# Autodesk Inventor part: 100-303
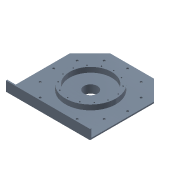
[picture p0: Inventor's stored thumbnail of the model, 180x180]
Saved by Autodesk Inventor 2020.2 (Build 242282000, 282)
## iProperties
Created: 2011-01
Part Number: 100-303
Document SubType Name: Modeling
Designer: F.Stasiak
Density: 1 g/cm^3
Material: Ogólny
Appearance: Stalowoniebieska
Company: Fabian Stasiak CAD Consulting
Manager: www.cadconsulting.pl
Author: F.Stasiak
Subject: Zbiór ćwiczeń. Autodesk Inventor 2020. Kurs podstawowy
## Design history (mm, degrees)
sketch "Szkic1"
  geometry: L1 (250, 0)-(-250, 0); L2 (-250, 0)-(-250, 500); L3 (-250, 500)-(250, 500); L4 (250, 500)-(250, 0); 2 further points
  constraints: 8 end point, 2 perpendicular, 1 coincident, 1 horizontal, 1 midpoint, 1 parallel
  dimensions: "d0" = 500 distance of L1.start L1.end; "d1" = 500 distance of L1.end L2.end
extrude "Wyciągnięcie proste1" new body sketch "Szkic1" distance "d2" = 8; taper "d3" = 0 deg
sketch "Szkic2"
  geometry: L1 (-250, 0)-(-250, 500) reference; L2 (250, 0)-(-250, 0) reference; L3 (250, 500)-(250, 0) reference; L4 (-250, 500)-(250, 500) reference; L5 (-250, 8)-(250, 8); L6 (-250, 0)-(-250, 500) reference; 1 further point
  constraints: 2 end point, 2 point on line, 1 perpendicular
  dimensions: "d4" = 8 distance between parallel lines of L5 L2 (= d2)
extrude "Wyciągnięcie proste2" join sketch "Szkic2" distance "d5" = 50; taper "d6" = 0 deg
chamfer "Faza1" distance "d7" = 120; stored, may be unused: second distance "d8" = 2, angle "d9" = 45 deg
sketch "Szkic3"
  geometry: L1 (130, 500)-(250, 380) reference; L2 (-130, 500)-(130, 500) reference; L3 (-250, 380)-(-130, 500) reference; L4 (-250, 8)-(-250, 380) reference; L5 (-250, 8)-(250, 8) reference; L6 (250, 380)-(250, 8) reference; L7 (0, 500)-(0, 8); C1 r 40 at (0, 254); 1 further point
  constraints: 3 midpoint, 2 end point, 1 centre point
  dimensions: "d10" = 80 diameter of C1
extrude "Wyciągnięcie proste3" cut sketch "Szkic3" extent not by distance; stored distance "d11" = 50; taper "d12" = 0 deg
sketch "Szkic4"
  geometry: C1 r 40 at (0, 254) reference; C2 r 60 at (0, 254); 1 further point
  constraints: 1 centre point
  dimensions: "d13" = 120 diameter of C2
extrude "Wyciągnięcie proste4" join sketch "Szkic4" distance "d14" = 40; taper "d15" = 0 deg
sketch "Szkic5"
  geometry: C1 r 6.5 at (0, 474) reference; 1 further point
hole "Hole1" sketch "Szkic5" at (0, 474) diameter "d16" = 13; stored, may be unused: countersink angle "d20" = 90 deg, drill point angle "d22" = 118 deg; dims "d17" = 6, "d18" = 4, "d19" = 2, "d21" = 8
pattern_circular "Szyk kołowy1" dims angle "d24" = 360 deg
sketch "Szkic6"
  geometry: C1 r 40 at (0, 254) reference; C2 r 150 at (0, 254); C3 r 125 at (0, 254); 1 further point
  constraints: 2 centre point, 2 coincident
  dimensions: "d26" = 300 diameter of C2; "d27" = 250 diameter of C3
extrude "Wyciągnięcie proste5" join sketch "Szkic6" distance "d28" = 30; taper "d29" = 0 deg
sketch "Szkic7" dims "d30" = 275
  geometry: C1 r 125 at (0, 0) reference; 2 further points
  constraints: 1 vertical alignment, 2 other
hole "Hole2" sketch "Szkic7" at (0, 137.5) diameter "d31" = 6.647; stored, may be unused: countersink angle "d35" = 90 deg, drill point angle "d37" = 118 deg; dims "d32" = 17, "d33" = 3.6, "d34" = 2, "d36" = 25
pattern_circular "Szyk kołowy2" dims angle "d39" = 360 deg
node "Otwory1"
node "Otwory2"
node "Bryła1"
node "Pętla rzutowana1"
node "Pętla rzutowana2"
node "Odniesienie1"
sketch "Szkic8"
  geometry: 14 further points
hole "Hole3" sketch "Szkic8" diameter "d41" = 4.917; stored, may be unused: countersink angle "d45" = 90 deg, drill point angle "d47" = 120 deg; dims "d42" = 9.5, "d43" = 4, "d44" = 2, "d46" = 12
sketch "Szkic9"
  geometry: 14 further points
hole "Hole4" sketch "Szkic9" diameter "d48" = 4.917; stored, may be unused: countersink angle "d52" = 90 deg, drill point angle "d54" = 120 deg; dims "d49" = 15, "d50" = 4, "d51" = 2, "d53" = 18
